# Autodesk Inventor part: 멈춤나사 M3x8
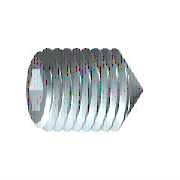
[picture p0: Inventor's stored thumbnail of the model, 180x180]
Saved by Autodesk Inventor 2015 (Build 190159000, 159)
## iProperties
IsCustomPart: 1
Created: 2012-02
Part Number: 멈춤나사 M3x8
Material: 강철, 연강
Description: 6각 소켓 머리 없는 멈춤 나사
Document SubType Name: Modeling
Standard: KS B 1028
Designer: test
Standards Organization: KS
Language: ko-KR
Size Designation: 원추점 M3x8
Categories: <MemberInstance><Categories><Category DisplayName="조임쇠" InternalName="e4da775c-781d-43d5-af7c-5136215cf5a6" Mnemonic="FSTN"><Category DisplayName="볼트" InternalN
Density: 1 g/cm^3
Appearance: 강철
Author: test
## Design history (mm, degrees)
sketch "스케치1"
  geometry: L1 (0, 0)-(5.5, 0); L2 (8, 0.866)-(8, 1.5); L3 (8, 1.5)-(0, 1.5); L4 (8, 0.866)-(6, 0.866); L5 (6, 0.866)-(5.5, 0); L6 (0, -0.3)-(0, 1.8) reference; L7 (0, 1.5)-(0, 0)
  constraints: 13 end point, 3 parallel, 1 collinear, 1 perpendicular, 1 point on line
  dimensions: "d0" = 2 distance of L2.start L4.end (= INTI); "d1" = 60 deg angle of L5 L1; "d2" = 3 diameter of L3 L1 (= NND); "d3" = 1.73205 diameter of L4 L1 (= 1.1547 x SW); "d5" = 8 distance from line of L2 L3.end (= NLG)
revolve "본체" sketch "스케치1" stored, may be unused: angle "d6" = 90 deg
sketch "스케치2"
  geometry: L1 (-0.433, 0.75)-(0.433, 0.75); L2 (0.433, 0.75)-(0.866, 0); L3 (0.866, 0)-(0.433, -0.75); L4 (0.433, -0.75)-(-0.433, -0.75); L5 (-0.433, -0.75)-(-0.866, 0); L6 (-0.866, 0)-(-0.433, 0.75); 3 further points
  constraints: 12 end point, 1 coincident, 1 horizontal, 13 other
extrude "슬롯" join sketch "스케치2" taper "d7" = 0 deg; stored distance "d21" = 10
workaxis "Work Axis1"
workplane "Work Plane1"
sketch "스케치4"
  geometry: L1 (0, 0.15)-(-1.35, 1.5) reference; L2 (0, -0.15)-(-1.35, -1.5) reference; L3 (-1.35, -1.5)-(0.15, 0); L4 (-1.35, 1.5)-(0.15, 0); 2 further points
  constraints: 4 end point, 1 coincident, 1 collinear, 1 horizontal alignment
node "작업점1"
body "Solid1"
feature "스레드" dims "d12" = 8 (= NLG), "d13" = 0
chamfer "모따기1" distance "d8" = 1.35 (computed from NND, SPD, FAWI); stored, may be unused: angle "d9" = 45 deg (= FAWI), second distance "d34" = 1.35 (computed from NND, SPD, FAWI)
chamfer "모따기2" distance "d10" = 0.30673 (= -0.5 x GD1 + 0.5 x NND); stored, may be unused: angle "d11" = 45 deg (= FAWI), second distance "d35" = 0.30673 (= -0.5 x GD1 + 0.5 x NND)
other parameters: "NND" = 3 [user parameter; used in 5 equation terms], "NLG" = 8 [user parameter; used in 2 equation terms], "INTI" = 2 [user parameter; used in 1 equation term], "FAWI" = 45 deg [user parameter; used in 4 equation terms], "SW" = 1.5 [user parameter; used in 2 equation terms], "GD1" = 2.38655 (= THREADDIA - 1.2269 x PTC) [user parameter; used in 2 equation terms], "d4" = 0, "FAWI1" = 45 deg [user parameter], "SPD" = 0.3 [user parameter; used in 2 equation terms], "d36" = 0, "d37" = 0, "GUL" = 0.30673 (= 0.61345 x PTC) [user parameter], "TOA" = 30 deg [user parameter], "THREADDIA" = 3 [user parameter; used in 1 equation term], "PTC" = 0.5 [user parameter; used in 4 equation terms], "GAL" = 0.30673 (= 0.61345 x PTC) [user parameter], "E0" = 1.7325 (= 1.155 x SW) [user parameter]
